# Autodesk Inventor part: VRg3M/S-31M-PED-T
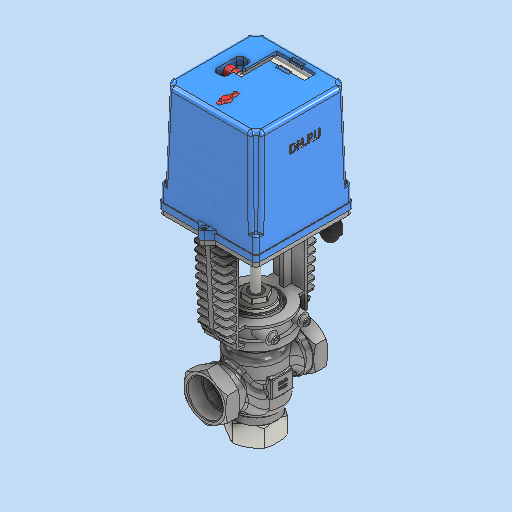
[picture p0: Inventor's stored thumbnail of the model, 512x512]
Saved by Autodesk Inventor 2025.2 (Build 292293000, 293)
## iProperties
Company: DN.RU
Created: 2026-04
Part Number: VRg3M/S-31M-PED-T
Material: Типовые
Description: D230-11267
Document SubType Name: Modeling
Designer: DN.RU
Mass: 4100 g
Surface Area: 2392.69 cm^2
Volume: 2662 cm^3
Density: 1.5397 g/cm^3
Appearance: По умолчанию
Title: Клапан регулирующий трехходовой Ду40 Ру25
Author: DN.RU
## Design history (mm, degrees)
derived "Сборка.iam"
node "Непосредственное редактирование1"
node "Твердое тело1"
node "Деталь 1.ipt:1" dims "d0" = 10
node "Деталь 2.ipt:1" dims "d0" = 10
node "Деталь 3.ipt:1" dims "d0" = 10
node "AS 1420 - метрическая M5 x 10:1" dims "d0" = 10
node "AS 1420 - метрическая M5 x 10:2" dims "d0" = 10
node "AS 1427 H - метрическая M3 x 8:1" dims "d0" = 10
node "AS 1427 H - метрическая M3 x 8:2" dims "d0" = 10
node "AS 1421 засверленный конец - метрическая M10 x 12 засверленн" dims "d0" = 10
node "AS 1421 засверленный конец - метрическая M10 x 12 засверленн" dims "d0" = 10
feature "Перенос1" dims "d3" = -1
other parameters: "d1" = 0, "d2" = 0
